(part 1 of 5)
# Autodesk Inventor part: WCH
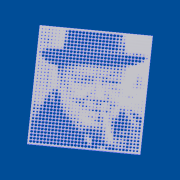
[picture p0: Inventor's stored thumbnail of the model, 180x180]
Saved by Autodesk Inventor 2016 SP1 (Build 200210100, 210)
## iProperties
Created: 2015-12
Part Number: WCH
Material: Všeobecné
Document SubType Name: Modeling
Designer: michlv
Mass: 501.095 g
Surface Area: 3130.91 cm^2
Volume: 501.095 cm^3
Density: 1 g/cm^3
Appearance: Studená bílá
LastSaveDate: 07.12.2015
Mass: 0,5 kg
FileName: WCH.ipt
Author: michlv
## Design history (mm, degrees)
sketch "Náčrt3"
  geometry: L1 (-5, -5)-(357, -5); L2 (357, -5)-(357, 390); L3 (357, 390)-(-5, 390); L4 (-5, 390)-(-5, -5)
  constraints: 8 end point, 2 parallel, 1 horizontal, 1 perpendicular
extrude "Vysunutí3" new body sketch "Náčrt3" distance "d8374" = 5; taper "d8375" = 0 deg
hole "Díra931" diameter "d8378" = 10; stored, may be unused: countersink angle "d8382" = 90 deg, drill point angle "d8384" = 0 deg; dims "d8376" = 10, "d8377" = 10, "d8379" = 6, "d8380" = 4, "d8381" = 2, "d8383" = 8
hole "Díra932" diameter "d8387" = 10; stored, may be unused: countersink angle "d8391" = 90 deg, drill point angle "d8393" = 0 deg; dims "d8385" = 21, "d8386" = 10, "d8388" = 6, "d8389" = 4, "d8390" = 2, "d8392" = 8
hole "Díra933" diameter "d8396" = 10; stored, may be unused: countersink angle "d8400" = 90 deg, drill point angle "d8402" = 0 deg; dims "d8394" = 32, "d8395" = 10, "d8397" = 6, "d8398" = 4, "d8399" = 2, "d8401" = 8
hole "Díra934" diameter "d8405" = 10; stored, may be unused: countersink angle "d8409" = 90 deg, drill point angle "d8411" = 0 deg; dims "d8403" = 43, "d8404" = 10, "d8406" = 6, "d8407" = 4, "d8408" = 2, "d8410" = 8
hole "Díra935" diameter "d8414" = 10; stored, may be unused: countersink angle "d8418" = 90 deg, drill point angle "d8420" = 0 deg; dims "d8412" = 54, "d8413" = 10, "d8415" = 6, "d8416" = 4, "d8417" = 2, "d8419" = 8
hole "Díra936" diameter "d8423" = 10; stored, may be unused: countersink angle "d8427" = 90 deg, drill point angle "d8429" = 0 deg; dims "d8421" = 65, "d8422" = 10, "d8424" = 6, "d8425" = 4, "d8426" = 2, "d8428" = 8
hole "Díra937" diameter "d8432" = 10; stored, may be unused: countersink angle "d8436" = 90 deg, drill point angle "d8438" = 0 deg; dims "d8430" = 76, "d8431" = 10, "d8433" = 6, "d8434" = 4, "d8435" = 2, "d8437" = 8
hole "Díra938" diameter "d8441" = 10; stored, may be unused: countersink angle "d8445" = 90 deg, drill point angle "d8447" = 0 deg; dims "d8439" = 87, "d8440" = 10, "d8442" = 6, "d8443" = 4, "d8444" = 2, "d8446" = 8
hole "Díra939" diameter "d8450" = 10; stored, may be unused: countersink angle "d8454" = 90 deg, drill point angle "d8456" = 0 deg; dims "d8448" = 98, "d8449" = 10, "d8451" = 6, "d8452" = 4, "d8453" = 2, "d8455" = 8
hole "Díra940" diameter "d8459" = 10; stored, may be unused: countersink angle "d8463" = 90 deg, drill point angle "d8465" = 0 deg; dims "d8457" = 109, "d8458" = 10, "d8460" = 6, "d8461" = 4, "d8462" = 2, "d8464" = 8
hole "Díra941" diameter "d8468" = 10; stored, may be unused: countersink angle "d8472" = 90 deg, drill point angle "d8474" = 0 deg; dims "d8466" = 120, "d8467" = 10, "d8469" = 6, "d8470" = 4, "d8471" = 2, "d8473" = 8
hole "Díra942" diameter "d8477" = 10; stored, may be unused: countersink angle "d8481" = 90 deg, drill point angle "d8483" = 0 deg; dims "d8475" = 131, "d8476" = 10, "d8478" = 6, "d8479" = 4, "d8480" = 2, "d8482" = 8
hole "Díra943" diameter "d8486" = 10; stored, may be unused: countersink angle "d8490" = 90 deg, drill point angle "d8492" = 0 deg; dims "d8484" = 142, "d8485" = 10, "d8487" = 6, "d8488" = 4, "d8489" = 2, "d8491" = 8
hole "Díra944" diameter "d8495" = 10; stored, may be unused: countersink angle "d8499" = 90 deg, drill point angle "d8501" = 0 deg; dims "d8493" = 153, "d8494" = 10, "d8496" = 6, "d8497" = 4, "d8498" = 2, "d8500" = 8
hole "Díra945" diameter "d8504" = 10; stored, may be unused: countersink angle "d8508" = 90 deg, drill point angle "d8510" = 0 deg; dims "d8502" = 164, "d8503" = 10, "d8505" = 6, "d8506" = 4, "d8507" = 2, "d8509" = 8
hole "Díra946" diameter "d8513" = 10; stored, may be unused: countersink angle "d8517" = 90 deg, drill point angle "d8519" = 0 deg; dims "d8511" = 175, "d8512" = 10, "d8514" = 6, "d8515" = 4, "d8516" = 2, "d8518" = 8
hole "Díra947" diameter "d8522" = 10; stored, may be unused: countersink angle "d8526" = 90 deg, drill point angle "d8528" = 0 deg; dims "d8520" = 186, "d8521" = 10, "d8523" = 6, "d8524" = 4, "d8525" = 2, "d8527" = 8
hole "Díra948" diameter "d8531" = 10; stored, may be unused: countersink angle "d8535" = 90 deg, drill point angle "d8537" = 0 deg; dims "d8529" = 197, "d8530" = 10, "d8532" = 6, "d8533" = 4, "d8534" = 2, "d8536" = 8
hole "Díra949" diameter "d8540" = 10; stored, may be unused: countersink angle "d8544" = 90 deg, drill point angle "d8546" = 0 deg; dims "d8538" = 208, "d8539" = 10, "d8541" = 6, "d8542" = 4, "d8543" = 2, "d8545" = 8
hole "Díra950" diameter "d8549" = 9.92157; stored, may be unused: countersink angle "d8553" = 90 deg, drill point angle "d8555" = 0 deg; dims "d8547" = 219, "d8548" = 10, "d8550" = 6, "d8551" = 4, "d8552" = 2, "d8554" = 8
hole "Díra951" diameter "d8558" = 6.54902; stored, may be unused: countersink angle "d8562" = 90 deg, drill point angle "d8564" = 0 deg; dims "d8556" = 230, "d8557" = 10, "d8559" = 6, "d8560" = 4, "d8561" = 2, "d8563" = 8
hole "Díra952" diameter "d8567" = 5.01961; stored, may be unused: countersink angle "d8571" = 90 deg, drill point angle "d8573" = 0 deg; dims "d8565" = 241, "d8566" = 10, "d8568" = 6, "d8569" = 4, "d8570" = 2, "d8572" = 8
hole "Díra953" diameter "d8576" = 8.66667; stored, may be unused: countersink angle "d8580" = 90 deg, drill point angle "d8582" = 0 deg; dims "d8574" = 252, "d8575" = 10, "d8577" = 6, "d8578" = 4, "d8579" = 2, "d8581" = 8
hole "Díra954" diameter "d8585" = 9.80392; stored, may be unused: countersink angle "d8589" = 90 deg, drill point angle "d8591" = 0 deg; dims "d8583" = 263, "d8584" = 10, "d8586" = 6, "d8587" = 4, "d8588" = 2, "d8590" = 8
hole "Díra955" diameter "d8594" = 10; stored, may be unused: countersink angle "d8598" = 90 deg, drill point angle "d8600" = 0 deg; dims "d8592" = 274, "d8593" = 10, "d8595" = 6, "d8596" = 4, "d8597" = 2, "d8599" = 8
hole "Díra956" diameter "d8603" = 8.23529; stored, may be unused: countersink angle "d8607" = 90 deg, drill point angle "d8609" = 0 deg; dims "d8601" = 285, "d8602" = 10, "d8604" = 6, "d8605" = 4, "d8606" = 2, "d8608" = 8
hole "Díra957" diameter "d8612" = 8.39216; stored, may be unused: countersink angle "d8616" = 90 deg, drill point angle "d8618" = 0 deg; dims "d8610" = 296, "d8611" = 10, "d8613" = 6, "d8614" = 4, "d8615" = 2, "d8617" = 8
hole "Díra958" diameter "d8621" = 9.41177; stored, may be unused: countersink angle "d8625" = 90 deg, drill point angle "d8627" = 0 deg; dims "d8619" = 307, "d8620" = 10, "d8622" = 6, "d8623" = 4, "d8624" = 2, "d8626" = 8
hole "Díra959" diameter "d8630" = 8.98039; stored, may be unused: countersink angle "d8634" = 90 deg, drill point angle "d8636" = 0 deg; dims "d8628" = 318, "d8629" = 10, "d8631" = 6, "d8632" = 4, "d8633" = 2, "d8635" = 8
hole "Díra960" diameter "d8639" = 7.4902; stored, may be unused: countersink angle "d8643" = 90 deg, drill point angle "d8645" = 0 deg; dims "d8637" = 329, "d8638" = 10, "d8640" = 6, "d8641" = 4, "d8642" = 2, "d8644" = 8
hole "Díra961" diameter "d8648" = 7.13725; stored, may be unused: countersink angle "d8652" = 90 deg, drill point angle "d8654" = 0 deg; dims "d8646" = 340, "d8647" = 10, "d8649" = 6, "d8650" = 4, "d8651" = 2, "d8653" = 8
hole "Díra962" diameter "d8657" = 6.98039; stored, may be unused: countersink angle "d8661" = 90 deg, drill point angle "d8663" = 0 deg; dims "d8655" = 351, "d8656" = 10, "d8658" = 6, "d8659" = 4, "d8660" = 2, "d8662" = 8
hole "Díra963" diameter "d8666" = 9.84314; stored, may be unused: countersink angle "d8670" = 90 deg, drill point angle "d8672" = 0 deg; dims "d8664" = 10, "d8665" = 21, "d8667" = 6, "d8668" = 4, "d8669" = 2, "d8671" = 8
hole "Díra964" diameter "d8675" = 9.92157; stored, may be unused: countersink angle "d8679" = 90 deg, drill point angle "d8681" = 0 deg; dims "d8673" = 21, "d8674" = 21, "d8676" = 6, "d8677" = 4, "d8678" = 2, "d8680" = 8
hole "Díra965" diameter "d8684" = 10; stored, may be unused: countersink angle "d8688" = 90 deg, drill point angle "d8690" = 0 deg; dims "d8682" = 32, "d8683" = 21, "d8685" = 6, "d8686" = 4, "d8687" = 2, "d8689" = 8
hole "Díra966" diameter "d8693" = 10; stored, may be unused: countersink angle "d8697" = 90 deg, drill point angle "d8699" = 0 deg; dims "d8691" = 43, "d8692" = 21, "d8694" = 6, "d8695" = 4, "d8696" = 2, "d8698" = 8
hole "Díra967" diameter "d8702" = 10; stored, may be unused: countersink angle "d8706" = 90 deg, drill point angle "d8708" = 0 deg; dims "d8700" = 54, "d8701" = 21, "d8703" = 6, "d8704" = 4, "d8705" = 2, "d8707" = 8
hole "Díra968" diameter "d8711" = 10; stored, may be unused: countersink angle "d8715" = 90 deg, drill point angle "d8717" = 0 deg; dims "d8709" = 65, "d8710" = 21, "d8712" = 6, "d8713" = 4, "d8714" = 2, "d8716" = 8
hole "Díra969" diameter "d8720" = 10; stored, may be unused: countersink angle "d8724" = 90 deg, drill point angle "d8726" = 0 deg; dims "d8718" = 76, "d8719" = 21, "d8721" = 6, "d8722" = 4, "d8723" = 2, "d8725" = 8
hole "Díra970" diameter "d8729" = 10; stored, may be unused: countersink angle "d8733" = 90 deg, drill point angle "d8735" = 0 deg; dims "d8727" = 87, "d8728" = 21, "d8730" = 6, "d8731" = 4, "d8732" = 2, "d8734" = 8
hole "Díra971" diameter "d8738" = 10; stored, may be unused: countersink angle "d8742" = 90 deg, drill point angle "d8744" = 0 deg; dims "d8736" = 98, "d8737" = 21, "d8739" = 6, "d8740" = 4, "d8741" = 2, "d8743" = 8
hole "Díra972" diameter "d8747" = 10; stored, may be unused: countersink angle "d8751" = 90 deg, drill point angle "d8753" = 0 deg; dims "d8745" = 109, "d8746" = 21, "d8748" = 6, "d8749" = 4, "d8750" = 2, "d8752" = 8
hole "Díra973" diameter "d8756" = 10; stored, may be unused: countersink angle "d8760" = 90 deg, drill point angle "d8762" = 0 deg; dims "d8754" = 120, "d8755" = 21, "d8757" = 6, "d8758" = 4, "d8759" = 2, "d8761" = 8
hole "Díra974" diameter "d8765" = 10; stored, may be unused: countersink angle "d8769" = 90 deg, drill point angle "d8771" = 0 deg; dims "d8763" = 131, "d8764" = 21, "d8766" = 6, "d8767" = 4, "d8768" = 2, "d8770" = 8
hole "Díra975" diameter "d8774" = 10; stored, may be unused: countersink angle "d8778" = 90 deg, drill point angle "d8780" = 0 deg; dims "d8772" = 142, "d8773" = 21, "d8775" = 6, "d8776" = 4, "d8777" = 2, "d8779" = 8
hole "Díra976" diameter "d8783" = 10; stored, may be unused: countersink angle "d8787" = 90 deg, drill point angle "d8789" = 0 deg; dims "d8781" = 153, "d8782" = 21, "d8784" = 6, "d8785" = 4, "d8786" = 2, "d8788" = 8
hole "Díra977" diameter "d8792" = 10; stored, may be unused: countersink angle "d8796" = 90 deg, drill point angle "d8798" = 0 deg; dims "d8790" = 164, "d8791" = 21, "d8793" = 6, "d8794" = 4, "d8795" = 2, "d8797" = 8
hole "Díra978" diameter "d8801" = 10; stored, may be unused: countersink angle "d8805" = 90 deg, drill point angle "d8807" = 0 deg; dims "d8799" = 175, "d8800" = 21, "d8802" = 6, "d8803" = 4, "d8804" = 2, "d8806" = 8
hole "Díra979" diameter "d8810" = 10; stored, may be unused: countersink angle "d8814" = 90 deg, drill point angle "d8816" = 0 deg; dims "d8808" = 186, "d8809" = 21, "d8811" = 6, "d8812" = 4, "d8813" = 2, "d8815" = 8
hole "Díra980" diameter "d8819" = 4.5098; stored, may be unused: countersink angle "d8823" = 90 deg, drill point angle "d8825" = 0 deg; dims "d8817" = 197, "d8818" = 21, "d8820" = 6, "d8821" = 4, "d8822" = 2, "d8824" = 8
hole "Díra981" diameter "d8828" = 10; stored, may be unused: countersink angle "d8832" = 90 deg, drill point angle "d8834" = 0 deg; dims "d8826" = 208, "d8827" = 21, "d8829" = 6, "d8830" = 4, "d8831" = 2, "d8833" = 8
hole "Díra982" diameter "d8837" = 10; stored, may be unused: countersink angle "d8841" = 90 deg, drill point angle "d8843" = 0 deg; dims "d8835" = 219, "d8836" = 21, "d8838" = 6, "d8839" = 4, "d8840" = 2, "d8842" = 8
hole "Díra983" diameter "d8846" = 10; stored, may be unused: countersink angle "d8850" = 90 deg, drill point angle "d8852" = 0 deg; dims "d8844" = 230, "d8845" = 21, "d8847" = 6, "d8848" = 4, "d8849" = 2, "d8851" = 8
hole "Díra984" diameter "d8855" = 10; stored, may be unused: countersink angle "d8859" = 90 deg, drill point angle "d8861" = 0 deg; dims "d8853" = 241, "d8854" = 21, "d8856" = 6, "d8857" = 4, "d8858" = 2, "d8860" = 8
hole "Díra985" diameter "d8864" = 8.54902; stored, may be unused: countersink angle "d8868" = 90 deg, drill point angle "d8870" = 0 deg; dims "d8862" = 252, "d8863" = 21, "d8865" = 6, "d8866" = 4, "d8867" = 2, "d8869" = 8
hole "Díra986" diameter "d8873" = 7.56863; stored, may be unused: countersink angle "d8877" = 90 deg, drill point angle "d8879" = 0 deg; dims "d8871" = 263, "d8872" = 21, "d8874" = 6, "d8875" = 4, "d8876" = 2, "d8878" = 8
hole "Díra987" diameter "d8882" = 7.76471; stored, may be unused: countersink angle "d8886" = 90 deg, drill point angle "d8888" = 0 deg; dims "d8880" = 274, "d8881" = 21, "d8883" = 6, "d8884" = 4, "d8885" = 2, "d8887" = 8
hole "Díra988" diameter "d8891" = 6.35294; stored, may be unused: countersink angle "d8895" = 90 deg, drill point angle "d8897" = 0 deg; dims "d8889" = 285, "d8890" = 21, "d8892" = 6, "d8893" = 4, "d8894" = 2, "d8896" = 8
hole "Díra989" diameter "d8900" = 7.01961; stored, may be unused: countersink angle "d8904" = 90 deg, drill point angle "d8906" = 0 deg; dims "d8898" = 296, "d8899" = 21, "d8901" = 6, "d8902" = 4, "d8903" = 2, "d8905" = 8
hole "Díra990" diameter "d8909" = 7.21569; stored, may be unused: countersink angle "d8913" = 90 deg, drill point angle "d8915" = 0 deg; dims "d8907" = 307, "d8908" = 21, "d8910" = 6, "d8911" = 4, "d8912" = 2, "d8914" = 8
hole "Díra991" diameter "d8918" = 9.01961; stored, may be unused: countersink angle "d8922" = 90 deg, drill point angle "d8924" = 0 deg; dims "d8916" = 318, "d8917" = 21, "d8919" = 6, "d8920" = 4, "d8921" = 2, "d8923" = 8
hole "Díra992" diameter "d8927" = 8.23529; stored, may be unused: countersink angle "d8931" = 90 deg, drill point angle "d8933" = 0 deg; dims "d8925" = 329, "d8926" = 21, "d8928" = 6, "d8929" = 4, "d8930" = 2, "d8932" = 8
hole "Díra993" diameter "d8936" = 7.80392; stored, may be unused: countersink angle "d8940" = 90 deg, drill point angle "d8942" = 0 deg; dims "d8934" = 340, "d8935" = 21, "d8937" = 6, "d8938" = 4, "d8939" = 2, "d8941" = 8
hole "Díra994" diameter "d8945" = 8.23529; stored, may be unused: countersink angle "d8949" = 90 deg, drill point angle "d8951" = 0 deg; dims "d8943" = 351, "d8944" = 21, "d8946" = 6, "d8947" = 4, "d8948" = 2, "d8950" = 8
hole "Díra995" diameter "d8954" = 9.68628; stored, may be unused: countersink angle "d8958" = 90 deg, drill point angle "d8960" = 0 deg; dims "d8952" = 10, "d8953" = 32, "d8955" = 6, "d8956" = 4, "d8957" = 2, "d8959" = 8
hole "Díra996" diameter "d8963" = 9.92157; stored, may be unused: countersink angle "d8967" = 90 deg, drill point angle "d8969" = 0 deg; dims "d8961" = 21, "d8962" = 32, "d8964" = 6, "d8965" = 4, "d8966" = 2, "d8968" = 8
hole "Díra997" diameter "d8972" = 10; stored, may be unused: countersink angle "d8976" = 90 deg, drill point angle "d8978" = 0 deg; dims "d8970" = 32, "d8971" = 32, "d8973" = 6, "d8974" = 4, "d8975" = 2, "d8977" = 8
hole "Díra998" diameter "d8981" = 10; stored, may be unused: countersink angle "d8985" = 90 deg, drill point angle "d8987" = 0 deg; dims "d8979" = 43, "d8980" = 32, "d8982" = 6, "d8983" = 4, "d8984" = 2, "d8986" = 8
hole "Díra999" diameter "d8990" = 10; stored, may be unused: countersink angle "d8994" = 90 deg, drill point angle "d8996" = 0 deg; dims "d8988" = 54, "d8989" = 32, "d8991" = 6, "d8992" = 4, "d8993" = 2, "d8995" = 8
hole "Díra1000" diameter "d8999" = 10; stored, may be unused: countersink angle "d9003" = 90 deg, drill point angle "d9005" = 0 deg; dims "d8997" = 65, "d8998" = 32, "d9000" = 6, "d9001" = 4, "d9002" = 2, "d9004" = 8
hole "Díra1001" diameter "d9008" = 10; stored, may be unused: countersink angle "d9012" = 90 deg, drill point angle "d9014" = 0 deg; dims "d9006" = 76, "d9007" = 32, "d9009" = 6, "d9010" = 4, "d9011" = 2, "d9013" = 8
hole "Díra1002" diameter "d9017" = 10; stored, may be unused: countersink angle "d9021" = 90 deg, drill point angle "d9023" = 0 deg; dims "d9015" = 87, "d9016" = 32, "d9018" = 6, "d9019" = 4, "d9020" = 2, "d9022" = 8
hole "Díra1003" diameter "d9026" = 10; stored, may be unused: countersink angle "d9030" = 90 deg, drill point angle "d9032" = 0 deg; dims "d9024" = 98, "d9025" = 32, "d9027" = 6, "d9028" = 4, "d9029" = 2, "d9031" = 8
hole "Díra1004" diameter "d9035" = 10; stored, may be unused: countersink angle "d9039" = 90 deg, drill point angle "d9041" = 0 deg; dims "d9033" = 109, "d9034" = 32, "d9036" = 6, "d9037" = 4, "d9038" = 2, "d9040" = 8
hole "Díra1005" diameter "d9044" = 10; stored, may be unused: countersink angle "d9048" = 90 deg, drill point angle "d9050" = 0 deg; dims "d9042" = 120, "d9043" = 32, "d9045" = 6, "d9046" = 4, "d9047" = 2, "d9049" = 8
hole "Díra1006" diameter "d9053" = 10; stored, may be unused: countersink angle "d9057" = 90 deg, drill point angle "d9059" = 0 deg; dims "d9051" = 131, "d9052" = 32, "d9054" = 6, "d9055" = 4, "d9056" = 2, "d9058" = 8
hole "Díra1007" diameter "d9062" = 10; stored, may be unused: countersink angle "d9066" = 90 deg, drill point angle "d9068" = 0 deg; dims "d9060" = 142, "d9061" = 32, "d9063" = 6, "d9064" = 4, "d9065" = 2, "d9067" = 8
hole "Díra1008" diameter "d9071" = 10; stored, may be unused: countersink angle "d9075" = 90 deg, drill point angle "d9077" = 0 deg; dims "d9069" = 153, "d9070" = 32, "d9072" = 6, "d9073" = 4, "d9074" = 2, "d9076" = 8
hole "Díra1009" diameter "d9080" = 10; stored, may be unused: countersink angle "d9084" = 90 deg, drill point angle "d9086" = 0 deg; dims "d9078" = 164, "d9079" = 32, "d9081" = 6, "d9082" = 4, "d9083" = 2, "d9085" = 8
hole "Díra1010" diameter "d9089" = 10; stored, may be unused: countersink angle "d9093" = 90 deg, drill point angle "d9095" = 0 deg; dims "d9087" = 175, "d9088" = 32, "d9090" = 6, "d9091" = 4, "d9092" = 2, "d9094" = 8
hole "Díra1011" diameter "d9098" = 4.86275; stored, may be unused: countersink angle "d9102" = 90 deg, drill point angle "d9104" = 0 deg; dims "d9096" = 186, "d9097" = 32, "d9099" = 6, "d9100" = 4, "d9101" = 2, "d9103" = 8
hole "Díra1012" diameter "d9107" = 2.90196; stored, may be unused: countersink angle "d9111" = 90 deg, drill point angle "d9113" = 0 deg; dims "d9105" = 197, "d9106" = 32, "d9108" = 6, "d9109" = 4, "d9110" = 2, "d9112" = 8
hole "Díra1013" diameter "d9116" = 10; stored, may be unused: countersink angle "d9120" = 90 deg, drill point angle "d9122" = 0 deg; dims "d9114" = 208, "d9115" = 32, "d9117" = 6, "d9118" = 4, "d9119" = 2, "d9121" = 8
hole "Díra1014" diameter "d9125" = 10; stored, may be unused: countersink angle "d9129" = 90 deg, drill point angle "d9131" = 0 deg; dims "d9123" = 219, "d9124" = 32, "d9126" = 6, "d9127" = 4, "d9128" = 2, "d9130" = 8
hole "Díra1015" diameter "d9134" = 9.68628; stored, may be unused: countersink angle "d9138" = 90 deg, drill point angle "d9140" = 0 deg; dims "d9132" = 230, "d9133" = 32, "d9135" = 6, "d9136" = 4, "d9137" = 2, "d9139" = 8
hole "Díra1016" diameter "d9143" = 8.23529; stored, may be unused: countersink angle "d9147" = 90 deg, drill point angle "d9149" = 0 deg; dims "d9141" = 241, "d9142" = 32, "d9144" = 6, "d9145" = 4, "d9146" = 2, "d9148" = 8
hole "Díra1017" diameter "d9152" = 4.5098; stored, may be unused: countersink angle "d9156" = 90 deg, drill point angle "d9158" = 0 deg; dims "d9150" = 252, "d9151" = 32, "d9153" = 6, "d9154" = 4, "d9155" = 2, "d9157" = 8
hole "Díra1018" diameter "d9161" = 2.66667; stored, may be unused: countersink angle "d9165" = 90 deg, drill point angle "d9167" = 0 deg; dims "d9159" = 263, "d9160" = 32, "d9162" = 6, "d9163" = 4, "d9164" = 2, "d9166" = 8
hole "Díra1019" diameter "d9170" = 4.98039; stored, may be unused: countersink angle "d9174" = 90 deg, drill point angle "d9176" = 0 deg; dims "d9168" = 274, "d9169" = 32, "d9171" = 6, "d9172" = 4, "d9173" = 2, "d9175" = 8
hole "Díra1020" diameter "d9179" = 6.33987; stored, may be unused: countersink angle "d9183" = 90 deg, drill point angle "d9185" = 0 deg; dims "d9177" = 285, "d9178" = 32, "d9180" = 6, "d9181" = 4, "d9182" = 2, "d9184" = 8
hole "Díra1021" diameter "d9188" = 7.60784; stored, may be unused: countersink angle "d9192" = 90 deg, drill point angle "d9194" = 0 deg; dims "d9186" = 296, "d9187" = 32, "d9189" = 6, "d9190" = 4, "d9191" = 2, "d9193" = 8
hole "Díra1022" diameter "d9197" = 6.92811; stored, may be unused: countersink angle "d9201" = 90 deg, drill point angle "d9203" = 0 deg; dims "d9195" = 307, "d9196" = 32, "d9198" = 6, "d9199" = 4, "d9200" = 2, "d9202" = 8
hole "Díra1023" diameter "d9206" = 8.98039; stored, may be unused: countersink angle "d9210" = 90 deg, drill point angle "d9212" = 0 deg; dims "d9204" = 318, "d9205" = 32, "d9207" = 6, "d9208" = 4, "d9209" = 2, "d9211" = 8
hole "Díra1024" diameter "d9215" = 8.39216; stored, may be unused: countersink angle "d9219" = 90 deg, drill point angle "d9221" = 0 deg; dims "d9213" = 329, "d9214" = 32, "d9216" = 6, "d9217" = 4, "d9218" = 2, "d9220" = 8
hole "Díra1025" diameter "d9224" = 7.29412; stored, may be unused: countersink angle "d9228" = 90 deg, drill point angle "d9230" = 0 deg; dims "d9222" = 340, "d9223" = 32, "d9225" = 6, "d9226" = 4, "d9227" = 2, "d9229" = 8
hole "Díra1026" diameter "d9233" = 8.35294; stored, may be unused: countersink angle "d9237" = 90 deg, drill point angle "d9239" = 0 deg; dims "d9231" = 351, "d9232" = 32, "d9234" = 6, "d9235" = 4, "d9236" = 2, "d9238" = 8
hole "Díra1027" diameter "d9242" = 9.60784; stored, may be unused: countersink angle "d9246" = 90 deg, drill point angle "d9248" = 0 deg; dims "d9240" = 10, "d9241" = 43, "d9243" = 6, "d9244" = 4, "d9245" = 2, "d9247" = 8
hole "Díra1028" diameter "d9251" = 9.92157; stored, may be unused: countersink angle "d9255" = 90 deg, drill point angle "d9257" = 0 deg; dims "d9249" = 21, "d9250" = 43, "d9252" = 6, "d9253" = 4, "d9254" = 2, "d9256" = 8
hole "Díra1029" diameter "d9260" = 10; stored, may be unused: countersink angle "d9264" = 90 deg, drill point angle "d9266" = 0 deg; dims "d9258" = 32, "d9259" = 43, "d9261" = 6, "d9262" = 4, "d9263" = 2, "d9265" = 8
hole "Díra1030" diameter "d9269" = 10; stored, may be unused: countersink angle "d9273" = 90 deg, drill point angle "d9275" = 0 deg; dims "d9267" = 43, "d9268" = 43, "d9270" = 6, "d9271" = 4, "d9272" = 2, "d9274" = 8
hole "Díra1031" diameter "d9278" = 10; stored, may be unused: countersink angle "d9282" = 90 deg, drill point angle "d9284" = 0 deg; dims "d9276" = 54, "d9277" = 43, "d9279" = 6, "d9280" = 4, "d9281" = 2, "d9283" = 8
hole "Díra1032" diameter "d9287" = 10; stored, may be unused: countersink angle "d9291" = 90 deg, drill point angle "d9293" = 0 deg; dims "d9285" = 65, "d9286" = 43, "d9288" = 6, "d9289" = 4, "d9290" = 2, "d9292" = 8
hole "Díra1033" diameter "d9296" = 10; stored, may be unused: countersink angle "d9300" = 90 deg, drill point angle "d9302" = 0 deg; dims "d9294" = 76, "d9295" = 43, "d9297" = 6, "d9298" = 4, "d9299" = 2, "d9301" = 8
hole "Díra1034" diameter "d9305" = 10; stored, may be unused: countersink angle "d9309" = 90 deg, drill point angle "d9311" = 0 deg; dims "d9303" = 87, "d9304" = 43, "d9306" = 6, "d9307" = 4, "d9308" = 2, "d9310" = 8
hole "Díra1035" diameter "d9314" = 10; stored, may be unused: countersink angle "d9318" = 90 deg, drill point angle "d9320" = 0 deg; dims "d9312" = 98, "d9313" = 43, "d9315" = 6, "d9316" = 4, "d9317" = 2, "d9319" = 8
hole "Díra1036" diameter "d9323" = 10; stored, may be unused: countersink angle "d9327" = 90 deg, drill point angle "d9329" = 0 deg; dims "d9321" = 109, "d9322" = 43, "d9324" = 6, "d9325" = 4, "d9326" = 2, "d9328" = 8
hole "Díra1037" diameter "d9332" = 10; stored, may be unused: countersink angle "d9336" = 90 deg, drill point angle "d9338" = 0 deg; dims "d9330" = 120, "d9331" = 43, "d9333" = 6, "d9334" = 4, "d9335" = 2, "d9337" = 8
hole "Díra1038" diameter "d9341" = 10; stored, may be unused: countersink angle "d9345" = 90 deg, drill point angle "d9347" = 0 deg; dims "d9339" = 131, "d9340" = 43, "d9342" = 6, "d9343" = 4, "d9344" = 2, "d9346" = 8
hole "Díra1039" diameter "d9350" = 10; stored, may be unused: countersink angle "d9354" = 90 deg, drill point angle "d9356" = 0 deg; dims "d9348" = 142, "d9349" = 43, "d9351" = 6, "d9352" = 4, "d9353" = 2, "d9355" = 8
hole "Díra1040" diameter "d9359" = 10; stored, may be unused: countersink angle "d9363" = 90 deg, drill point angle "d9365" = 0 deg; dims "d9357" = 153, "d9358" = 43, "d9360" = 6, "d9361" = 4, "d9362" = 2, "d9364" = 8
hole "Díra1041" diameter "d9368" = 10; stored, may be unused: countersink angle "d9372" = 90 deg, drill point angle "d9374" = 0 deg; dims "d9366" = 164, "d9367" = 43, "d9369" = 6, "d9370" = 4, "d9371" = 2, "d9373" = 8
hole "Díra1042" diameter "d9377" = 9.41177; stored, may be unused: countersink angle "d9381" = 90 deg, drill point angle "d9383" = 0 deg; dims "d9375" = 175, "d9376" = 43, "d9378" = 6, "d9379" = 4, "d9380" = 2, "d9382" = 8
hole "Díra1043" diameter "d9386" = 5.17647; stored, may be unused: countersink angle "d9390" = 90 deg, drill point angle "d9392" = 0 deg; dims "d9384" = 186, "d9385" = 43, "d9387" = 6, "d9388" = 4, "d9389" = 2, "d9391" = 8
hole "Díra1044" diameter "d9395" = 8.23529; stored, may be unused: countersink angle "d9399" = 90 deg, drill point angle "d9401" = 0 deg; dims "d9393" = 197, "d9394" = 43, "d9396" = 6, "d9397" = 4, "d9398" = 2, "d9400" = 8
hole "Díra1045" diameter "d9404" = 9.84314; stored, may be unused: countersink angle "d9408" = 90 deg, drill point angle "d9410" = 0 deg; dims "d9402" = 208, "d9403" = 43, "d9405" = 6, "d9406" = 4, "d9407" = 2, "d9409" = 8
hole "Díra1046" diameter "d9413" = 10; stored, may be unused: countersink angle "d9417" = 90 deg, drill point angle "d9419" = 0 deg; dims "d9411" = 219, "d9412" = 43, "d9414" = 6, "d9415" = 4, "d9416" = 2, "d9418" = 8
hole "Díra1047" diameter "d9422" = 8.90196; stored, may be unused: countersink angle "d9426" = 90 deg, drill point angle "d9428" = 0 deg; dims "d9420" = 230, "d9421" = 43, "d9423" = 6, "d9424" = 4, "d9425" = 2, "d9427" = 8
hole "Díra1048" diameter "d9431" = 6.66667; stored, may be unused: countersink angle "d9435" = 90 deg, drill point angle "d9437" = 0 deg; dims "d9429" = 241, "d9430" = 43, "d9432" = 6, "d9433" = 4, "d9434" = 2, "d9436" = 8
hole "Díra1049" diameter "d9440" = 2.15686; stored, may be unused: countersink angle "d9444" = 90 deg, drill point angle "d9446" = 0 deg; dims "d9438" = 252, "d9439" = 43, "d9441" = 6, "d9442" = 4, "d9443" = 2, "d9445" = 8
hole "Díra1050" diameter "d9449" = 6.19608; stored, may be unused: countersink angle "d9453" = 90 deg, drill point angle "d9455" = 0 deg; dims "d9447" = 274, "d9448" = 43, "d9450" = 6, "d9451" = 4, "d9452" = 2, "d9454" = 8
hole "Díra1051" diameter "d9458" = 7.37255; stored, may be unused: countersink angle "d9462" = 90 deg, drill point angle "d9464" = 0 deg; dims "d9456" = 285, "d9457" = 43, "d9459" = 6, "d9460" = 4, "d9461" = 2, "d9463" = 8
hole "Díra1052" diameter "d9467" = 5.2549; stored, may be unused: countersink angle "d9471" = 90 deg, drill point angle "d9473" = 0 deg; dims "d9465" = 296, "d9466" = 43, "d9468" = 6, "d9469" = 4, "d9470" = 2, "d9472" = 8
hole "Díra1053" diameter "d9476" = 7.01961; stored, may be unused: countersink angle "d9480" = 90 deg, drill point angle "d9482" = 0 deg; dims "d9474" = 307, "d9475" = 43, "d9477" = 6, "d9478" = 4, "d9479" = 2, "d9481" = 8, "d16117" = 318
hole "Díra1054" diameter "d9485" = 9.01961; stored, may be unused: countersink angle "d9489" = 90 deg, drill point angle "d9491" = 0 deg; dims "d9483" = 318, "d9484" = 43, "d9486" = 6, "d9487" = 4, "d9488" = 2, "d9490" = 8
hole "Díra1055" diameter "d9494" = 7.84314; stored, may be unused: countersink angle "d9498" = 90 deg, drill point angle "d9500" = 0 deg; dims "d9492" = 329, "d9493" = 43, "d9495" = 6, "d9496" = 4, "d9497" = 2, "d9499" = 8
hole "Díra1056" diameter "d9503" = 7.56863; stored, may be unused: countersink angle "d9507" = 90 deg, drill point angle "d9509" = 0 deg; dims "d9501" = 340, "d9502" = 43, "d9504" = 6, "d9505" = 4, "d9506" = 2, "d9508" = 8
hole "Díra1057" diameter "d9512" = 7.96078; stored, may be unused: countersink angle "d9516" = 90 deg, drill point angle "d9518" = 0 deg; dims "d9510" = 351, "d9511" = 43, "d9513" = 6, "d9514" = 4, "d9515" = 2, "d9517" = 8
hole "Díra1058" diameter "d9521" = 9.52941; stored, may be unused: countersink angle "d9525" = 90 deg, drill point angle "d9527" = 0 deg; dims "d9519" = 10, "d9520" = 54, "d9522" = 6, "d9523" = 4, "d9524" = 2, "d9526" = 8
hole "Díra1059" diameter "d9530" = 9.68628; stored, may be unused: countersink angle "d9534" = 90 deg, drill point angle "d9536" = 0 deg; dims "d9528" = 21, "d9529" = 54, "d9531" = 6, "d9532" = 4, "d9533" = 2, "d9535" = 8
hole "Díra1060" diameter "d9539" = 10; stored, may be unused: countersink angle "d9543" = 90 deg, drill point angle "d9545" = 0 deg; dims "d9537" = 32, "d9538" = 54, "d9540" = 6, "d9541" = 4, "d9542" = 2, "d9544" = 8
hole "Díra1061" diameter "d9548" = 10; stored, may be unused: countersink angle "d9552" = 90 deg, drill point angle "d9554" = 0 deg; dims "d9546" = 43, "d9547" = 54, "d9549" = 6, "d9550" = 4, "d9551" = 2, "d9553" = 8
hole "Díra1062" diameter "d9557" = 10; stored, may be unused: countersink angle "d9561" = 90 deg, drill point angle "d9563" = 0 deg; dims "d9555" = 54, "d9556" = 54, "d9558" = 6, "d9559" = 4, "d9560" = 2, "d9562" = 8
hole "Díra1063" diameter "d9566" = 10; stored, may be unused: countersink angle "d9570" = 90 deg, drill point angle "d9572" = 0 deg; dims "d9564" = 65, "d9565" = 54, "d9567" = 6, "d9568" = 4, "d9569" = 2, "d9571" = 8
hole "Díra1064" diameter "d9575" = 10; stored, may be unused: countersink angle "d9579" = 90 deg, drill point angle "d9581" = 0 deg; dims "d9573" = 76, "d9574" = 54, "d9576" = 6, "d9577" = 4, "d9578" = 2, "d9580" = 8
hole "Díra1065" diameter "d9584" = 10; stored, may be unused: countersink angle "d9588" = 90 deg, drill point angle "d9590" = 0 deg; dims "d9582" = 87, "d9583" = 54, "d9585" = 6, "d9586" = 4, "d9587" = 2, "d9589" = 8
hole "Díra1066" diameter "d9593" = 10; stored, may be unused: countersink angle "d9597" = 90 deg, drill point angle "d9599" = 0 deg; dims "d9591" = 98, "d9592" = 54, "d9594" = 6, "d9595" = 4, "d9596" = 2, "d9598" = 8
hole "Díra1067" diameter "d9602" = 10; stored, may be unused: countersink angle "d9606" = 90 deg, drill point angle "d9608" = 0 deg; dims "d9600" = 109, "d9601" = 54, "d9603" = 6, "d9604" = 4, "d9605" = 2, "d9607" = 8
hole "Díra1068" diameter "d9611" = 10; stored, may be unused: countersink angle "d9615" = 90 deg, drill point angle "d9617" = 0 deg; dims "d9609" = 120, "d9610" = 54, "d9612" = 6, "d9613" = 4, "d9614" = 2, "d9616" = 8
hole "Díra1069" diameter "d9620" = 10; stored, may be unused: countersink angle "d9624" = 90 deg, drill point angle "d9626" = 0 deg; dims "d9618" = 131, "d9619" = 54, "d9621" = 6, "d9622" = 4, "d9623" = 2, "d9625" = 8
hole "Díra1070" diameter "d9629" = 10; stored, may be unused: countersink angle "d9633" = 90 deg, drill point angle "d9635" = 0 deg; dims "d9627" = 142, "d9628" = 54, "d9630" = 6, "d9631" = 4, "d9632" = 2, "d9634" = 8
hole "Díra1071" diameter "d9638" = 10; stored, may be unused: countersink angle "d9642" = 90 deg, drill point angle "d9644" = 0 deg; dims "d9636" = 153, "d9637" = 54, "d9639" = 6, "d9640" = 4, "d9641" = 2, "d9643" = 8
hole "Díra1072" diameter "d9647" = 10; stored, may be unused: countersink angle "d9651" = 90 deg, drill point angle "d9653" = 0 deg; dims "d9645" = 164, "d9646" = 54, "d9648" = 6, "d9649" = 4, "d9650" = 2, "d9652" = 8
hole "Díra1073" diameter "d9656" = 9.09804; stored, may be unused: countersink angle "d9660" = 90 deg, drill point angle "d9662" = 0 deg; dims "d9654" = 175, "d9655" = 54, "d9657" = 6, "d9658" = 4, "d9659" = 2, "d9661" = 8
hole "Díra1074" diameter "d9665" = 9.29412; stored, may be unused: countersink angle "d9669" = 90 deg, drill point angle "d9671" = 0 deg; dims "d9663" = 186, "d9664" = 54, "d9666" = 6, "d9667" = 4, "d9668" = 2, "d9670" = 8
hole "Díra1075" diameter "d9674" = 9.2549; stored, may be unused: countersink angle "d9678" = 90 deg, drill point angle "d9680" = 0 deg; dims "d9672" = 197, "d9673" = 54, "d9675" = 6, "d9676" = 4, "d9677" = 2, "d9679" = 8
hole "Díra1076" diameter "d9683" = 8.98039; stored, may be unused: countersink angle "d9687" = 90 deg, drill point angle "d9689" = 0 deg; dims "d9681" = 208, "d9682" = 54, "d9684" = 6, "d9685" = 4, "d9686" = 2, "d9688" = 8
hole "Díra1077" diameter "d9692" = 8.90196; stored, may be unused: countersink angle "d9696" = 90 deg, drill point angle "d9698" = 0 deg; dims "d9690" = 219, "d9691" = 54, "d9693" = 6, "d9694" = 4, "d9695" = 2, "d9697" = 8
hole "Díra1078" diameter "d9701" = 8.54902; stored, may be unused: countersink angle "d9705" = 90 deg, drill point angle "d9707" = 0 deg; dims "d9699" = 230, "d9700" = 54, "d9702" = 6, "d9703" = 4, "d9704" = 2, "d9706" = 8
hole "Díra1079" diameter "d9710" = 5.68628; stored, may be unused: countersink angle "d9714" = 90 deg, drill point angle "d9716" = 0 deg; dims "d9708" = 241, "d9709" = 54, "d9711" = 6, "d9712" = 4, "d9713" = 2, "d9715" = 8
hole "Díra1080" diameter "d9719" = 0.70588; stored, may be unused: countersink angle "d9723" = 90 deg, drill point angle "d9725" = 0 deg; dims "d9717" = 252, "d9718" = 54, "d9720" = 6, "d9721" = 4, "d9722" = 2, "d9724" = 8
hole "Díra1081" diameter "d9728" = 0.39216; stored, may be unused: countersink angle "d9732" = 90 deg, drill point angle "d9734" = 0 deg; dims "d9726" = 263, "d9727" = 54, "d9729" = 6, "d9730" = 4, "d9731" = 2, "d9733" = 8
hole "Díra1082" diameter "d9737" = 8.54902; stored, may be unused: countersink angle "d9741" = 90 deg, drill point angle "d9743" = 0 deg; dims "d9735" = 274, "d9736" = 54, "d9738" = 6, "d9739" = 4, "d9740" = 2, "d9742" = 8
hole "Díra1083" diameter "d9746" = 9.80392; stored, may be unused: countersink angle "d9750" = 90 deg, drill point angle "d9752" = 0 deg; dims "d9744" = 285, "d9745" = 54, "d9747" = 6, "d9748" = 4, "d9749" = 2, "d9751" = 8
hole "Díra1084" diameter "d9755" = 9.92157; stored, may be unused: countersink angle "d9759" = 90 deg, drill point angle "d9761" = 0 deg; dims "d9753" = 296, "d9754" = 54, "d9756" = 6, "d9757" = 4, "d9758" = 2, "d9760" = 8
hole "Díra1085" diameter "d9764" = 8.90196; stored, may be unused: countersink angle "d9768" = 90 deg, drill point angle "d9770" = 0 deg; dims "d9762" = 307, "d9763" = 54, "d9765" = 6, "d9766" = 4, "d9767" = 2, "d9769" = 8
hole "Díra1086" diameter "d9773" = 8.90196; stored, may be unused: countersink angle "d9777" = 90 deg, drill point angle "d9779" = 0 deg; dims "d9771" = 318, "d9772" = 54, "d9774" = 6, "d9775" = 4, "d9776" = 2, "d9778" = 8
hole "Díra1087" diameter "d9782" = 7.52941; stored, may be unused: countersink angle "d9786" = 90 deg, drill point angle "d9788" = 0 deg; dims "d9780" = 329, "d9781" = 54, "d9783" = 6, "d9784" = 4, "d9785" = 2, "d9787" = 8
hole "Díra1088" diameter "d9791" = 7.29412; stored, may be unused: countersink angle "d9795" = 90 deg, drill point angle "d9797" = 0 deg; dims "d9789" = 340, "d9790" = 54, "d9792" = 6, "d9793" = 4, "d9794" = 2, "d9796" = 8
hole "Díra1089" diameter "d9800" = 6.70588; stored, may be unused: countersink angle "d9804" = 90 deg, drill point angle "d9806" = 0 deg; dims "d9798" = 351, "d9799" = 54, "d9801" = 6, "d9802" = 4, "d9803" = 2, "d9805" = 8
hole "Díra1090" diameter "d9809" = 9.29412; stored, may be unused: countersink angle "d9813" = 90 deg, drill point angle "d9815" = 0 deg; dims "d9807" = 10, "d9808" = 65, "d9810" = 6, "d9811" = 4, "d9812" = 2, "d9814" = 8
hole "Díra1091" diameter "d9818" = 9.52941; stored, may be unused: countersink angle "d9822" = 90 deg, drill point angle "d9824" = 0 deg; dims "d9816" = 21, "d9817" = 65, "d9819" = 6, "d9820" = 4, "d9821" = 2, "d9823" = 8
hole "Díra1092" diameter "d9827" = 9.92157; stored, may be unused: countersink angle "d9831" = 90 deg, drill point angle "d9833" = 0 deg; dims "d9825" = 32, "d9826" = 65, "d9828" = 6, "d9829" = 4, "d9830" = 2, "d9832" = 8
hole "Díra1093" diameter "d9836" = 10; stored, may be unused: countersink angle "d9840" = 90 deg, drill point angle "d9842" = 0 deg; dims "d9834" = 43, "d9835" = 65, "d9837" = 6, "d9838" = 4, "d9839" = 2, "d9841" = 8
hole "Díra1094" diameter "d9845" = 10; stored, may be unused: countersink angle "d9849" = 90 deg, drill point angle "d9851" = 0 deg; dims "d9843" = 54, "d9844" = 65, "d9846" = 6, "d9847" = 4, "d9848" = 2, "d9850" = 8
hole "Díra1095" diameter "d9854" = 10; stored, may be unused: countersink angle "d9858" = 90 deg, drill point angle "d9860" = 0 deg; dims "d9852" = 65, "d9853" = 65, "d9855" = 6, "d9856" = 4, "d9857" = 2, "d9859" = 8
hole "Díra1096" diameter "d9863" = 10; stored, may be unused: countersink angle "d9867" = 90 deg, drill point angle "d9869" = 0 deg; dims "d9861" = 76, "d9862" = 65, "d9864" = 6, "d9865" = 4, "d9866" = 2, "d9868" = 8
hole "Díra1097" diameter "d9872" = 10; stored, may be unused: countersink angle "d9876" = 90 deg, drill point angle "d9878" = 0 deg; dims "d9870" = 87, "d9871" = 65, "d9873" = 6, "d9874" = 4, "d9875" = 2, "d9877" = 8
hole "Díra1098" diameter "d9881" = 10; stored, may be unused: countersink angle "d9885" = 90 deg, drill point angle "d9887" = 0 deg; dims "d9879" = 98, "d9880" = 65, "d9882" = 6, "d9883" = 4, "d9884" = 2, "d9886" = 8
hole "Díra1099" diameter "d9890" = 10; stored, may be unused: countersink angle "d9894" = 90 deg, drill point angle "d9896" = 0 deg; dims "d9888" = 109, "d9889" = 65, "d9891" = 6, "d9892" = 4, "d9893" = 2, "d9895" = 8
hole "Díra1100" diameter "d9899" = 10; stored, may be unused: countersink angle "d9903" = 90 deg, drill point angle "d9905" = 0 deg; dims "d9897" = 120, "d9898" = 65, "d9900" = 6, "d9901" = 4, "d9902" = 2, "d9904" = 8
hole "Díra1101" diameter "d9908" = 10; stored, may be unused: countersink angle "d9912" = 90 deg, drill point angle "d9914" = 0 deg; dims "d9906" = 131, "d9907" = 65, "d9909" = 6, "d9910" = 4, "d9911" = 2, "d9913" = 8
hole "Díra1102" diameter "d9917" = 10; stored, may be unused: countersink angle "d9921" = 90 deg, drill point angle "d9923" = 0 deg; dims "d9915" = 142, "d9916" = 65, "d9918" = 6, "d9919" = 4, "d9920" = 2, "d9922" = 8
hole "Díra1103" diameter "d9926" = 8.90196; stored, may be unused: countersink angle "d9930" = 90 deg, drill point angle "d9932" = 0 deg; dims "d9924" = 153, "d9925" = 65, "d9927" = 6, "d9928" = 4, "d9929" = 2, "d9931" = 8
hole "Díra1104" diameter "d9935" = 6; stored, may be unused: countersink angle "d9939" = 90 deg, drill point angle "d9941" = 0 deg; dims "d9933" = 164, "d9934" = 65, "d9936" = 6, "d9937" = 4, "d9938" = 2, "d9940" = 8
hole "Díra1105" diameter "d9944" = 8.07843; stored, may be unused: countersink angle "d9948" = 90 deg, drill point angle "d9950" = 0 deg; dims "d9942" = 175, "d9943" = 65, "d9945" = 6, "d9946" = 4, "d9947" = 2, "d9949" = 8
hole "Díra1106" diameter "d9953" = 8.98039; stored, may be unused: countersink angle "d9957" = 90 deg, drill point angle "d9959" = 0 deg; dims "d9951" = 186, "d9952" = 65, "d9954" = 6, "d9955" = 4, "d9956" = 2, "d9958" = 8
hole "Díra1107" diameter "d9962" = 9.09804; stored, may be unused: countersink angle "d9966" = 90 deg, drill point angle "d9968" = 0 deg; dims "d9960" = 197, "d9961" = 65, "d9963" = 6, "d9964" = 4, "d9965" = 2, "d9967" = 8
hole "Díra1108" diameter "d9971" = 8.82353; stored, may be unused: countersink angle "d9975" = 90 deg, drill point angle "d9977" = 0 deg; dims "d9969" = 208, "d9970" = 65, "d9972" = 6, "d9973" = 4, "d9974" = 2, "d9976" = 8
hole "Díra1109" diameter "d9980" = 8.58823; stored, may be unused: countersink angle "d9984" = 90 deg, drill point angle "d9986" = 0 deg; dims "d9978" = 219, "d9979" = 65, "d9981" = 6, "d9982" = 4, "d9983" = 2, "d9985" = 8
hole "Díra1110" diameter "d9989" = 8.62745; stored, may be unused: countersink angle "d9993" = 90 deg, drill point angle "d9995" = 0 deg; dims "d9987" = 230, "d9988" = 65, "d9990" = 6, "d9991" = 4, "d9992" = 2, "d9994" = 8
hole "Díra1111" diameter "d9998" = 5.21569; stored, may be unused: countersink angle "d10002" = 90 deg, drill point angle "d10004" = 0 deg; dims "d9996" = 241, "d9997" = 65, "d9999" = 6, "d10000" = 4, "d10001" = 2, "d10003" = 8
hole "Díra1112" diameter "d10007" = 3.81699; stored, may be unused: countersink angle "d10011" = 90 deg, drill point angle "d10013" = 0 deg; dims "d10005" = 263, "d10006" = 65, "d10008" = 6, "d10009" = 4, "d10010" = 2, "d10012" = 8
hole "Díra1113" diameter "d10016" = 10; stored, may be unused: countersink angle "d10020" = 90 deg, drill point angle "d10022" = 0 deg; dims "d10014" = 274, "d10015" = 65, "d10017" = 6, "d10018" = 4, "d10019" = 2, "d10021" = 8
hole "Díra1114" diameter "d10025" = 8.35294; stored, may be unused: countersink angle "d10029" = 90 deg, drill point angle "d10031" = 0 deg; dims "d10023" = 285, "d10024" = 65, "d10026" = 6, "d10027" = 4, "d10028" = 2, "d10030" = 8
hole "Díra1115" diameter "d10034" = 6.58824; stored, may be unused: countersink angle "d10038" = 90 deg, drill point angle "d10040" = 0 deg; dims "d10032" = 296, "d10033" = 65, "d10035" = 6, "d10036" = 4, "d10037" = 2, "d10039" = 8
hole "Díra1116" diameter "d10043" = 7.84314; stored, may be unused: countersink angle "d10047" = 90 deg, drill point angle "d10049" = 0 deg; dims "d10041" = 307, "d10042" = 65, "d10044" = 6, "d10045" = 4, "d10046" = 2, "d10048" = 8
hole "Díra1117" diameter "d10052" = 8.35294; stored, may be unused: countersink angle "d10056" = 90 deg, drill point angle "d10058" = 0 deg; dims "d10050" = 318, "d10051" = 65, "d10053" = 6, "d10054" = 4, "d10055" = 2, "d10057" = 8
hole "Díra1118" diameter "d10061" = 7.17647; stored, may be unused: countersink angle "d10065" = 90 deg, drill point angle "d10067" = 0 deg; dims "d10059" = 329, "d10060" = 65, "d10062" = 6, "d10063" = 4, "d10064" = 2, "d10066" = 8
hole "Díra1119" diameter "d10070" = 6.39216; stored, may be unused: countersink angle "d10074" = 90 deg, drill point angle "d10076" = 0 deg; dims "d10068" = 340, "d10069" = 65, "d10071" = 6, "d10072" = 4, "d10073" = 2, "d10075" = 8
hole "Díra1120" diameter "d10079" = 6.5098; stored, may be unused: countersink angle "d10083" = 90 deg, drill point angle "d10085" = 0 deg; dims "d10077" = 351, "d10078" = 65, "d10080" = 6, "d10081" = 4, "d10082" = 2, "d10084" = 8
hole "Díra1121" diameter "d10088" = 9.01961; stored, may be unused: countersink angle "d10092" = 90 deg, drill point angle "d10094" = 0 deg; dims "d10086" = 10, "d10087" = 76, "d10089" = 6, "d10090" = 4, "d10091" = 2, "d10093" = 8
hole "Díra1122" diameter "d10097" = 9.41177; stored, may be unused: countersink angle "d10101" = 90 deg, drill point angle "d10103" = 0 deg; dims "d10095" = 21, "d10096" = 76, "d10098" = 6, "d10099" = 4, "d10100" = 2, "d10102" = 8
hole "Díra1123" diameter "d10106" = 9.84314; stored, may be unused: countersink angle "d10110" = 90 deg, drill point angle "d10112" = 0 deg; dims "d10104" = 32, "d10105" = 76, "d10107" = 6, "d10108" = 4, "d10109" = 2, "d10111" = 8
hole "Díra1124" diameter "d10115" = 10; stored, may be unused: countersink angle "d10119" = 90 deg, drill point angle "d10121" = 0 deg; dims "d10113" = 43, "d10114" = 76, "d10116" = 6, "d10117" = 4, "d10118" = 2, "d10120" = 8
hole "Díra1125" diameter "d10124" = 10; stored, may be unused: countersink angle "d10128" = 90 deg, drill point angle "d10130" = 0 deg; dims "d10122" = 54, "d10123" = 76, "d10125" = 6, "d10126" = 4, "d10127" = 2, "d10129" = 8
hole "Díra1126" diameter "d10133" = 10; stored, may be unused: countersink angle "d10137" = 90 deg, drill point angle "d10139" = 0 deg; dims "d10131" = 65, "d10132" = 76, "d10134" = 6, "d10135" = 4, "d10136" = 2, "d10138" = 8
hole "Díra1127" diameter "d10142" = 10; stored, may be unused: countersink angle "d10146" = 90 deg, drill point angle "d10148" = 0 deg; dims "d10140" = 76, "d10141" = 76, "d10143" = 6, "d10144" = 4, "d10145" = 2, "d10147" = 8
hole "Díra1128" diameter "d10151" = 10; stored, may be unused: countersink angle "d10155" = 90 deg, drill point angle "d10157" = 0 deg; dims "d10149" = 87, "d10150" = 76, "d10152" = 6, "d10153" = 4, "d10154" = 2, "d10156" = 8
hole "Díra1129" diameter "d10160" = 10; stored, may be unused: countersink angle "d10164" = 90 deg, drill point angle "d10166" = 0 deg; dims "d10158" = 98, "d10159" = 76, "d10161" = 6, "d10162" = 4, "d10163" = 2, "d10165" = 8
hole "Díra1130" diameter "d10169" = 10; stored, may be unused: countersink angle "d10173" = 90 deg, drill point angle "d10175" = 0 deg; dims "d10167" = 109, "d10168" = 76, "d10170" = 6, "d10171" = 4, "d10172" = 2, "d10174" = 8
hole "Díra1131" diameter "d10178" = 10; stored, may be unused: countersink angle "d10182" = 90 deg, drill point angle "d10184" = 0 deg; dims "d10176" = 120, "d10177" = 76, "d10179" = 6, "d10180" = 4, "d10181" = 2, "d10183" = 8
hole "Díra1132" diameter "d10187" = 10; stored, may be unused: countersink angle "d10191" = 90 deg, drill point angle "d10193" = 0 deg; dims "d10185" = 131, "d10186" = 76, "d10188" = 6, "d10189" = 4, "d10190" = 2, "d10192" = 8
hole "Díra1133" diameter "d10196" = 8.78431; stored, may be unused: countersink angle "d10200" = 90 deg, drill point angle "d10202" = 0 deg; dims "d10194" = 142, "d10195" = 76, "d10197" = 6, "d10198" = 4, "d10199" = 2, "d10201" = 8
hole "Díra1134" diameter "d10205" = 5.13725; stored, may be unused: countersink angle "d10209" = 90 deg, drill point angle "d10211" = 0 deg; dims "d10203" = 153, "d10204" = 76, "d10206" = 6, "d10207" = 4, "d10208" = 2, "d10210" = 8
hole "Díra1135" diameter "d10214" = 6.98039; stored, may be unused: countersink angle "d10218" = 90 deg, drill point angle "d10220" = 0 deg; dims "d10212" = 164, "d10213" = 76, "d10215" = 6, "d10216" = 4, "d10217" = 2, "d10219" = 8
hole "Díra1136" diameter "d10223" = 5.84314; stored, may be unused: countersink angle "d10227" = 90 deg, drill point angle "d10229" = 0 deg; dims "d10221" = 175, "d10222" = 76, "d10224" = 6, "d10225" = 4, "d10226" = 2, "d10228" = 8
hole "Díra1137" diameter "d10232" = 4.86275; stored, may be unused: countersink angle "d10236" = 90 deg, drill point angle "d10238" = 0 deg; dims "d10230" = 186, "d10231" = 76, "d10233" = 6, "d10234" = 4, "d10235" = 2, "d10237" = 8
hole "Díra1138" diameter "d10241" = 6.19608; stored, may be unused: countersink angle "d10245" = 90 deg, drill point angle "d10247" = 0 deg; dims "d10239" = 197, "d10240" = 76, "d10242" = 6, "d10243" = 4, "d10244" = 2, "d10246" = 8
hole "Díra1139" diameter "d10250" = 5.72549; stored, may be unused: countersink angle "d10254" = 90 deg, drill point angle "d10256" = 0 deg; dims "d10248" = 208, "d10249" = 76, "d10251" = 6, "d10252" = 4, "d10253" = 2, "d10255" = 8
hole "Díra1140" diameter "d10259" = 6.19608; stored, may be unused: countersink angle "d10263" = 90 deg, drill point angle "d10265" = 0 deg; dims "d10257" = 219, "d10258" = 76, "d10260" = 6, "d10261" = 4, "d10262" = 2, "d10264" = 8
hole "Díra1141" diameter "d10268" = 6.5098; stored, may be unused: countersink angle "d10272" = 90 deg, drill point angle "d10274" = 0 deg; dims "d10266" = 230, "d10267" = 76, "d10269" = 6, "d10270" = 4, "d10271" = 2, "d10273" = 8
hole "Díra1142" diameter "d10277" = 3.4902; stored, may be unused: countersink angle "d10281" = 90 deg, drill point angle "d10283" = 0 deg; dims "d10275" = 241, "d10276" = 76, "d10278" = 6, "d10279" = 4, "d10280" = 2, "d10282" = 8
hole "Díra1143" diameter "d10286" = 4.54902; stored, may be unused: countersink angle "d10290" = 90 deg, drill point angle "d10292" = 0 deg; dims "d10284" = 263, "d10285" = 76, "d10287" = 6, "d10288" = 4, "d10289" = 2, "d10291" = 8
hole "Díra1144" diameter "d10295" = 10; stored, may be unused: countersink angle "d10299" = 90 deg, drill point angle "d10301" = 0 deg; dims "d10293" = 274, "d10294" = 76, "d10296" = 6, "d10297" = 4, "d10298" = 2, "d10300" = 8
hole "Díra1145" diameter "d10304" = 10; stored, may be unused: countersink angle "d10308" = 90 deg, drill point angle "d10310" = 0 deg; dims "d10302" = 285, "d10303" = 76, "d10305" = 6, "d10306" = 4, "d10307" = 2, "d10309" = 8
hole "Díra1146" diameter "d10313" = 9.92157; stored, may be unused: countersink angle "d10317" = 90 deg, drill point angle "d10319" = 0 deg; dims "d10311" = 296, "d10312" = 76, "d10314" = 6, "d10315" = 4, "d10316" = 2, "d10318" = 8
hole "Díra1147" diameter "d10322" = 9.09804; stored, may be unused: countersink angle "d10326" = 90 deg, drill point angle "d10328" = 0 deg; dims "d10320" = 307, "d10321" = 76, "d10323" = 6, "d10324" = 4, "d10325" = 2, "d10327" = 8
hole "Díra1148" diameter "d10331" = 8.19608; stored, may be unused: countersink angle "d10335" = 90 deg, drill point angle "d10337" = 0 deg; dims "d10329" = 318, "d10330" = 76, "d10332" = 6, "d10333" = 4, "d10334" = 2, "d10336" = 8
hole "Díra1149" diameter "d10340" = 7.29412; stored, may be unused: countersink angle "d10344" = 90 deg, drill point angle "d10346" = 0 deg; dims "d10338" = 329, "d10339" = 76, "d10341" = 6, "d10342" = 4, "d10343" = 2, "d10345" = 8
hole "Díra1150" diameter "d10349" = 7.92157; stored, may be unused: countersink angle "d10353" = 90 deg, drill point angle "d10355" = 0 deg; dims "d10347" = 340, "d10348" = 76, "d10350" = 6, "d10351" = 4, "d10352" = 2, "d10354" = 8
